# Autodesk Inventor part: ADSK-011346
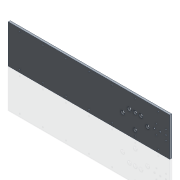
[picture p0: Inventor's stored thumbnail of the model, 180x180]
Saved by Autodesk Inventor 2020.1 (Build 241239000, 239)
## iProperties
Created: 1999-11
Part Number: ADSK-011346
Material: Pearson Aluminium
Description: carriage support plate
Document SubType Name: Modeling
Designer: glanglot
Density: 2.71 g/cm^3
Appearance: Pearson-Aluminum
Mass: 9198.5 g
Surface Area: 5798.87 cm^2
Volume: 3394.28 cm^3
Company: Pearson Packaging Systems
Control State: 0
Master: False
Checked Out: False
Shininess: 35.0
Length Units: 11269
Angle Units: 11279
Time Units: 11290
Mass Units: 11283
Length Display Precision: 3
Angle Display Precision: 2
Compacted: True
Material Desc: SHEET,ALUM,0.500
Material_number: A101291
Cutlength: 420 SI  (10.0 X 42.0)
DocNumber: ADSK-011346.ipt
Folder: 01 - Themengebiete\Simplification\04-Packaging machine\
VDS_Category: 3D Komponenten
Dimensions: 1067x254x12,7 mm
Mass: 9,198 kg
Density: 2.71
Volumn: 3429.395001333496
Area: 5798.651953795184
PropertySet Name: Model Information
Author: glanglot
Revision Number: -
Title: carriage support plate
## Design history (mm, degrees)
node "Rectangular Pattern1" dims "d30" = 20, "d32" = 216, "d33" = 60, "d35" = 152.4
node "Solide1"
  node "Extrusion1" dims "d2" = 12.7, "d3" = 0
  node "Hole1" dims "d12" = 6.6, "d13" = 9.525, "d14" = 6.35, "d15" = 60 deg, "d16" = 19.05, "d17" = 118 deg, "d80" = 6
  node "Hole2" dims "d24" = 9, "d25" = 9.525, "d26" = 6.35, "d27" = 60 deg, "d28" = 19.05, "d29" = 118 deg, "d81" = 6
  node "Hole3" dims "d38" = 6.6, "d39" = 9.525, "d40" = 6.35, "d41" = 60 deg, "d42" = 19.05, "d43" = 118 deg, "d82" = 6
  node "Hole4" dims "d56" = 6.6, "d57" = 9.525, "d58" = 6.35, "d59" = 60 deg, "d60" = 19.05, "d61" = 118 deg, "d83" = 6
  node "Hole5" dims "d74" = 25, "d75" = 9.525, "d76" = 6.35, "d77" = 60 deg, "d78" = 19.05, "d79" = 118 deg, "d84" = 6
sketch "Sketch1"
  geometry: L1 (0, 254)-(1067, 254); L2 (1067, 254)-(1067, 0); L3 (1067, 0)-(0, 0); L4 (0, 0)-(0, 254); 1 further point
  constraints: 8 end point, 2 parallel, 1 coincident, 1 horizontal, 1 perpendicular
  dimensions: "d0" = 254 distance of L3.end L1.start; "d1" = 1067 distance of L2.end L3.end
sketch "Sketch2"
  geometry: L1 (-1067, 254)-(0, 254) reference; L2 (-1067, 0)-(-1067, 254) reference; 1 further point
  dimensions: "d4" = 228.75 distance from line of point (-838.25, 235) L2 (computed from d1, d35, d33); "d11" = 19 distance from line of point (-838.25, 235) L1
sketch "Sketch6"
  geometry: L1 (1067, 0)-(0, 0) reference; L2 (1067, 254)-(1067, 0) reference; 6 further points
  constraints: 3 horizontal alignment
  dimensions: "d62" = 38 distance of point (838.4, 154) point (800.4, 154); "d63" = 38 distance of point (876.4, 154) point (838.4, 154) (= d62); "d64" = 44.5 horizontal distance of point (800.4, 154) point (755.9, 113); "d65" = 44.5 horizontal distance of point (920.9, 113) point (876.4, 154) (= d64); "d66" = 82.5 horizontal distance of point (838.4, 53) point (920.9, 113); "d67" = 41 vertical distance of point (800.4, 154) point (755.9, 113); "d71" = 60 vertical distance of point (838.4, 53) point (920.9, 113); "d72" = 228.6 distance from line of L2 point (838.4, 53); "d73" = 53 distance from line of L1 point (838.4, 53)
sketch "Sketch3"
  geometry: L1 (1067, 254)-(1067, 0) reference; 4 further points
  constraints: 3 horizontal alignment, 1 midpoint
  dimensions: "d19" = 25 distance from line of L1 point (1042, 127); "d21" = 38 distance of point (1004, 127) point (1042, 127); "d22" = 38 distance of point (966, 127) point (1004, 127) (= d21)
sketch "Sketch5"
  geometry: C1 r 4.5 at (1042, 127) reference; 4 further points
  dimensions: "d48" = 32 distance of point (1042, 159) C1.centre (= d49); "d49" = 32 distance of point (1042, 95) C1.centre; "d50" = 32 vertical distance of point (978.5, 159) C1.centre (= d49); "d51" = 32 vertical distance of point (978.5, 95) C1.centre (= d49); "d52" = 63.5 horizontal distance of C1.centre point (978.5, 159); "d53" = 63.5 horizontal distance of point (978.5, 95) C1.centre; "d54" = 63.5 distance of point (978.5, 159) point (1042, 159); "d55" = 63.5 distance of point (978.5, 95) point (1042, 95)
node "Corps solides"
node "Corps surfaciques"
sketch "Sketch4"
  geometry: C1 r 3.3 at (838.25, 19) reference; C2 r 3.3 at (838.25, 235) reference; 2 further points
  constraints: 2 horizontal alignment
  dimensions: "d36" = 152.4 distance of point (990.65, 235) C2.centre (= d35); "d37" = 152.4 distance of point (990.65, 19) C1.centre (= d35)
